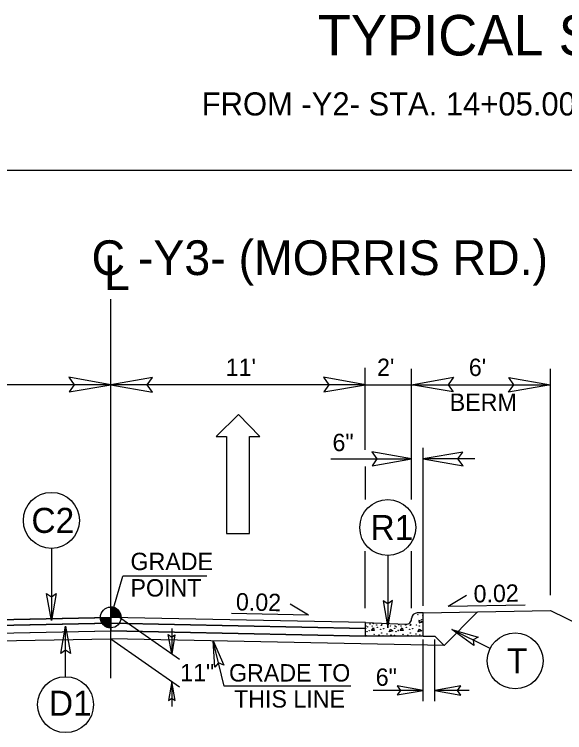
# Model space of a CAD drawing. Extents: x 1487909 to 1489267, y 497866 to 499814.
# Drawn here: x 1488976.3 to 1489000.07, y 498034.86 to 498065.88 of the extents above; entities that cross this region are included whole.
import ezdxf

# ---------------------------------------------------------------- set-up
doc = ezdxf.new("R2010")
doc.units = 0
for name, color, linetype in [('Old_Level_10', 7, 'Continuous'), ('Prop Dimension', 7, 'Continuous'), ('Prop Dimension Text', 7, 'Continuous'), ('Prop Lane Arrow CELL', 7, 'Continuous'), ('Prop Shade Light', 7, 'Continuous'), ('Prop Terminator CELL', 7, 'Continuous'), ('Scratch_Level_1', 7, 'Continuous'), ('Typical Curb CELL', 7, 'Continuous'), ('Typical Detail Wedge2 CELL', 7, 'Continuous'), ('Typical Grade Point Symbol CELL', 7, 'Continuous'), ('Typical Hinge Slope Arterial CELL', 7, 'Continuous'), ('Typical Hinge Slope Interstate CELL', 7, 'Continuous'), ('Typical ID Circle CELL', 7, 'Continuous'), ('Typical Pavement Slope CELL', 7, 'Continuous'), ('Typical Pavement Slope Information CELL', 7, 'Continuous'), ('Typical Terminator CELL', 7, 'Continuous'), ('Typical Text Grade Point CELL', 7, 'Continuous'), ('Typical Text ID Circle CELL', 7, 'Continuous')]:
    doc.layers.add(name, color=color, linetype=linetype)

msp = doc.modelspace()

# ---------------------------------------------------------------- linework, layer by layer
at = {"layer": 'Old_Level_10'}
for p, q in [((1488980.464, 498039.58), (1488969.464, 498039.36)), ((1488980.464, 498039.247), (1488980.464, 498039.58)), ((1488980.464, 498039.58), (1488980.464, 498039.247)), ((1488991.464, 498039.36), (1488980.464, 498039.58)), ((1488980.464, 498039.58), (1488980.464, 498039.58)), ((1488974.963, 498039.137), (1488980.464, 498039.247)), ((1488980.464, 498039.247), (1488985.964, 498039.137)), ((1488985.964, 498039.137), (1488991.464, 498039.027)), ((1488991.464, 498039.027), (1488991.464, 498039.36))]:
    msp.add_line(p, q, dxfattribs=at)
at = {"layer": 'Prop Dimension'}
for p, q in [((1488980.464, 498037.215), (1488980.464, 498053.576)), ((1488991.463, 498047.07), (1488991.463, 498050.612)), ((1488993.464, 498044.924), (1488993.464, 498050.568)), ((1488999.464, 498040.793), (1488999.464, 498050.568)), ((1488980.464, 498049.887), (1488969.464, 498049.887)), ((1488991.464, 498049.887), (1488980.464, 498049.887)), ((1488991.464, 498049.887), (1488993.464, 498049.887)), ((1488993.464, 498049.887), (1488999.464, 498049.887)), ((1488993.963, 498040.339), (1488993.963, 498047.152)), ((1488989.968, 498046.681), (1488993.463, 498046.681)), ((1488996.2, 498046.681), (1488993.963, 498046.681)), ((1488991.464, 498044.924), (1488991.464, 498046.354)), ((1488991.463, 498040.231), (1488991.463, 498042.701)), ((1488993.463, 498040.231), (1488993.463, 498042.701)), ((1488985.367, 498036.869), (1488984.883, 498038.826)), ((1488993.963, 498036.221), (1488993.963, 498038.875)), ((1488994.463, 498036.221), (1488994.463, 498038.875)), ((1488990.84, 498036.869), (1488985.367, 498036.869)), ((1488993.963, 498036.68), (1488991.802, 498036.68)), ((1488995.95, 498036.68), (1488994.463, 498036.68))]:
    msp.add_line(p, q, dxfattribs=at)
at = {"layer": 'Prop Dimension Text'}
for p in [(1488980.464, 498039.83), (1488984.608, 498041.62)]:
    msp.add_line(p, (1488980.989, 498041.62), dxfattribs=at)
at = {"layer": 'Prop Lane Arrow CELL'}
for p, q in [((1488985.979, 498048.6), (1488985.019, 498047.655)), ((1488986.909, 498047.655), (1488985.979, 498048.6)), ((1488985.019, 498047.655), (1488985.469, 498047.655)), ((1488985.469, 498047.655), (1488985.469, 498043.455)), ((1488986.459, 498043.455), (1488986.459, 498047.655)), ((1488986.459, 498047.655), (1488986.909, 498047.655)), ((1488985.469, 498043.455), (1488986.459, 498043.455))]:
    msp.add_line(p, q, dxfattribs=at)
at = {"layer": 'Prop Shade Light'}
for p, q in [((1488980.464, 498039.83), (1488969.464, 498039.61)), ((1488980.464, 498039.58), (1488980.464, 498039.83)), ((1488991.464, 498039.61), (1488980.464, 498039.83)), ((1488980.464, 498039.83), (1488980.464, 498039.58)), ((1488969.464, 498039.36), (1488980.464, 498039.58)), ((1488980.464, 498039.58), (1488991.464, 498039.36)), ((1488991.464, 498039.36), (1488991.464, 498039.61))]:
    msp.add_line(p, q, dxfattribs=at)
at = {"layer": 'Prop Terminator CELL'}
for points in [[(1488978.664, 498049.577), (1488980.464, 498049.887), (1488978.654, 498050.207), (1488978.884, 498049.887)], [(1488982.264, 498050.197), (1488980.464, 498049.887), (1488982.274, 498049.567), (1488982.044, 498049.887)], [(1488989.664, 498049.577), (1488991.464, 498049.887), (1488989.654, 498050.207), (1488989.884, 498049.887)], [(1488995.264, 498049.577), (1488993.464, 498049.887), (1488995.274, 498050.207), (1488995.044, 498049.887)], [(1488997.664, 498050.197), (1488999.464, 498049.887), (1488997.654, 498049.567), (1488997.884, 498049.887)], [(1488991.753, 498046.387), (1488993.463, 498046.681), (1488991.744, 498046.985), (1488991.962, 498046.681)], [(1488995.673, 498046.976), (1488993.963, 498046.681), (1488995.683, 498046.377), (1488995.464, 498046.681)], [(1488984.965, 498037.687), (1488984.883, 498038.826), (1488985.349, 498037.776), (1488985.12, 498037.867)], [(1488992.838, 498036.487), (1488993.963, 498036.68), (1488992.832, 498036.88), (1488992.976, 498036.68)], [(1488995.588, 498036.874), (1488994.463, 498036.68), (1488995.594, 498036.48), (1488995.451, 498036.68)]]:
    msp.add_lwpolyline(points, close=True, dxfattribs=at)
at = {"layer": 'Scratch_Level_1'}
msp.add_line((1488899.964, 498059.154), (1489049.964, 498059.154), dxfattribs=at)
at = {"layer": 'Typical Curb CELL'}
for p, q in [((1488993.963, 498040.027), (1488993.703, 498040.027)), ((1488993.963, 498039.027), (1488993.963, 498040.027)), ((1488993.463, 498039.777), (1488993.463, 498039.787)), ((1488991.464, 498039.027), (1488991.464, 498039.61)), ((1488991.464, 498039.61), (1488993.214, 498039.537)), ((1488993.773, 498039.694), (1488993.789, 498039.603)), ((1488993.927, 498039.649), (1488993.773, 498039.694)), ((1488993.789, 498039.603), (1488993.927, 498039.649)), ((1488991.724, 498039.267), (1488991.81, 498039.386)), ((1488991.845, 498039.273), (1488991.724, 498039.267)), ((1488991.81, 498039.386), (1488991.845, 498039.273)), ((1488992.489, 498039.216), (1488992.552, 498039.33)), ((1488992.655, 498039.255), (1488992.489, 498039.216)), ((1488992.552, 498039.33), (1488992.655, 498039.255)), ((1488992.974, 498039.267), (1488993.059, 498039.386)), ((1488993.094, 498039.273), (1488992.974, 498039.267)), ((1488993.059, 498039.386), (1488993.094, 498039.273)), ((1488993.738, 498039.216), (1488993.801, 498039.33)), ((1488993.904, 498039.255), (1488993.738, 498039.216)), ((1488993.801, 498039.33), (1488993.904, 498039.255)), ((1488993.963, 498039.027), (1488991.464, 498039.027))]:
    msp.add_line(p, q, dxfattribs=at)
for centre in [(1488993.733, 498039.951), (1488993.898, 498039.734), (1488993.95, 498039.917), (1488991.497, 498039.461), (1488991.553, 498039.427), (1488991.662, 498039.552), (1488991.759, 498039.467), (1488991.804, 498039.569), (1488991.953, 498039.506), (1488991.981, 498039.404), (1488992.158, 498039.49), (1488992.175, 498039.54), (1488992.432, 498039.512), (1488992.552, 498039.461), (1488992.746, 498039.461), (1488992.802, 498039.427), (1488992.911, 498039.521), (1488993.008, 498039.467), (1488993.202, 498039.506), (1488993.23, 498039.404), (1488993.407, 498039.49), (1488993.425, 498039.54), (1488993.681, 498039.512), (1488993.801, 498039.461), (1488991.48, 498039.364), (1488991.537, 498039.221), (1488991.633, 498039.267), (1488991.844, 498039.101), (1488992.13, 498039.318), (1488992.164, 498039.164), (1488992.256, 498039.347), (1488992.398, 498039.113), (1488992.729, 498039.364), (1488992.786, 498039.221), (1488992.882, 498039.267), (1488993.093, 498039.101), (1488993.379, 498039.318), (1488993.413, 498039.164), (1488993.505, 498039.347), (1488993.647, 498039.113), (1488991.474, 498039.056), (1488991.685, 498039.033), (1488992.05, 498039.079), (1488992.221, 498039.05), (1488992.569, 498039.073), (1488992.723, 498039.056), (1488992.934, 498039.033), (1488993.299, 498039.079), (1488993.47, 498039.05), (1488993.818, 498039.073)]:
    msp.add_circle(centre, 0.00802, dxfattribs=at)
for centre, start, end in [((1488993.703, 498039.787), 90, 180), ((1488993.224, 498039.777), 267.6155, 0)]:
    msp.add_arc(centre, 0.24, start, end, dxfattribs=at)
at = {"layer": 'Typical Detail Wedge2 CELL'}
for p, q in [((1488980.464, 498040.11), (1488983.428, 498038.034)), ((1488983.096, 498039.351), (1488983.096, 498038.266)), ((1488980.464, 498038.914), (1488983.428, 498036.839)), ((1488983.107, 498037.063), (1488983.107, 498035.979))]:
    msp.add_line(p, q, dxfattribs=at)
at = {"layer": 'Typical Grade Point Symbol CELL'}
for p, q in [((1488980.464, 498039.83), (1488980.464, 498040.278)), ((1488980.016, 498039.83), (1488980.464, 498039.83)), ((1488980.463, 498039.383), (1488980.464, 498039.83)), ((1488980.464, 498039.83), (1488980.463, 498039.383)), ((1488980.911, 498039.83), (1488980.464, 498039.83))]:
    msp.add_line(p, q, dxfattribs=at)
for points in [[(1488980.468, 498040.278), (1488980.468, 498040.278), (1488980.468, 498039.83)], [(1488980.477, 498040.278), (1488980.477, 498039.83)], [(1488980.486, 498040.277), (1488980.486, 498039.83)], [(1488980.494, 498040.277), (1488980.494, 498039.83)], [(1488980.503, 498040.276), (1488980.503, 498039.83)], [(1488980.512, 498040.275), (1488980.512, 498039.83)], [(1488980.521, 498040.274), (1488980.521, 498039.83)], [(1488980.53, 498040.273), (1488980.53, 498039.83)], [(1488980.539, 498040.272), (1488980.539, 498039.83)], [(1488980.548, 498040.27), (1488980.548, 498039.83)], [(1488980.557, 498040.268), (1488980.557, 498039.83)], [(1488980.566, 498040.266), (1488980.566, 498039.83)], [(1488980.575, 498040.264), (1488980.575, 498039.83)], [(1488980.584, 498040.261), (1488980.584, 498039.83)], [(1488980.593, 498040.259), (1488980.593, 498039.83)], [(1488980.602, 498040.256), (1488980.602, 498039.83)], [(1488980.611, 498040.253), (1488980.611, 498039.83)], [(1488980.62, 498040.25), (1488980.62, 498039.83)], [(1488980.629, 498040.246), (1488980.629, 498039.83)], [(1488980.638, 498040.242), (1488980.638, 498039.83)], [(1488980.647, 498040.238), (1488980.647, 498039.83)], [(1488980.656, 498040.234), (1488980.656, 498039.83)], [(1488980.665, 498040.23), (1488980.665, 498039.83)], [(1488980.673, 498040.225), (1488980.673, 498039.83)], [(1488980.682, 498040.22), (1488980.682, 498039.83)], [(1488980.691, 498040.215), (1488980.691, 498039.83)], [(1488980.7, 498040.21), (1488980.7, 498039.83)], [(1488980.709, 498040.204), (1488980.709, 498039.83)], [(1488980.718, 498040.198), (1488980.718, 498039.83)], [(1488980.727, 498040.191), (1488980.727, 498039.83)], [(1488980.736, 498040.185), (1488980.736, 498039.83)], [(1488980.745, 498040.178), (1488980.745, 498039.83)], [(1488980.754, 498040.17), (1488980.754, 498039.83)], [(1488980.763, 498040.163), (1488980.763, 498039.83)], [(1488980.772, 498040.155), (1488980.772, 498039.83)], [(1488980.781, 498040.146), (1488980.781, 498039.83)], [(1488980.79, 498040.137), (1488980.79, 498039.83)], [(1488980.799, 498040.127), (1488980.799, 498039.83)], [(1488980.808, 498040.116), (1488980.808, 498039.83)], [(1488980.817, 498040.105), (1488980.817, 498039.83)], [(1488980.826, 498040.093), (1488980.826, 498039.83)], [(1488980.835, 498040.08), (1488980.835, 498039.83)], [(1488980.844, 498040.066), (1488980.844, 498039.83)], [(1488980.852, 498040.051), (1488980.852, 498039.83)], [(1488980.861, 498040.035), (1488980.861, 498039.83)], [(1488980.018, 498039.83), (1488980.018, 498039.782)], [(1488980.027, 498039.83), (1488980.027, 498039.729)], [(1488980.036, 498039.83), (1488980.036, 498039.697)], [(1488980.045, 498039.83), (1488980.045, 498039.67)], [(1488980.054, 498039.83), (1488980.054, 498039.649)], [(1488980.063, 498039.83), (1488980.063, 498039.63)], [(1488980.072, 498039.83), (1488980.072, 498039.613)], [(1488980.081, 498039.83), (1488980.081, 498039.598)], [(1488980.09, 498039.83), (1488980.09, 498039.584)], [(1488980.099, 498039.83), (1488980.099, 498039.571)], [(1488980.108, 498039.83), (1488980.108, 498039.559)], [(1488980.116, 498039.83), (1488980.116, 498039.548)], [(1488980.125, 498039.83), (1488980.125, 498039.537)], [(1488980.134, 498039.83), (1488980.134, 498039.527)], [(1488980.143, 498039.83), (1488980.143, 498039.517)], [(1488980.152, 498039.83), (1488980.152, 498039.508)], [(1488980.161, 498039.83), (1488980.161, 498039.5)], [(1488980.17, 498039.83), (1488980.17, 498039.492)], [(1488980.179, 498039.83), (1488980.179, 498039.484)], [(1488980.188, 498039.83), (1488980.188, 498039.477)], [(1488980.197, 498039.83), (1488980.197, 498039.47)], [(1488980.206, 498039.83), (1488980.206, 498039.464)], [(1488980.215, 498039.83), (1488980.215, 498039.458)], [(1488980.224, 498039.83), (1488980.224, 498039.452)], [(1488980.233, 498039.83), (1488980.233, 498039.446)], [(1488980.242, 498039.83), (1488980.242, 498039.441)], [(1488980.251, 498039.83), (1488980.251, 498039.436)], [(1488980.26, 498039.83), (1488980.26, 498039.431)], [(1488980.269, 498039.83), (1488980.269, 498039.427)], [(1488980.278, 498039.83), (1488980.278, 498039.423)], [(1488980.287, 498039.83), (1488980.287, 498039.419)], [(1488980.295, 498039.83), (1488980.295, 498039.416)], [(1488980.304, 498039.83), (1488980.304, 498039.412)], [(1488980.313, 498039.83), (1488980.313, 498039.409)], [(1488980.322, 498039.83), (1488980.322, 498039.406)], [(1488980.331, 498039.83), (1488980.331, 498039.403)], [(1488980.34, 498039.83), (1488980.34, 498039.401)], [(1488980.349, 498039.83), (1488980.349, 498039.398)], [(1488980.358, 498039.83), (1488980.358, 498039.396)], [(1488980.367, 498039.83), (1488980.367, 498039.394)], [(1488980.376, 498039.83), (1488980.376, 498039.392)], [(1488980.385, 498039.83), (1488980.385, 498039.39)], [(1488980.394, 498039.83), (1488980.394, 498039.389)], [(1488980.403, 498039.83), (1488980.403, 498039.387)], [(1488980.412, 498039.83), (1488980.412, 498039.386)], [(1488980.421, 498039.83), (1488980.421, 498039.385)], [(1488980.43, 498039.83), (1488980.43, 498039.384)], [(1488980.439, 498039.83), (1488980.439, 498039.384)], [(1488980.448, 498039.83), (1488980.448, 498039.383)], [(1488980.457, 498039.83), (1488980.457, 498039.383), (1488980.457, 498039.383)], [(1488980.87, 498040.016), (1488980.87, 498039.83)], [(1488980.879, 498039.995), (1488980.879, 498039.83)], [(1488980.888, 498039.97), (1488980.888, 498039.83)], [(1488980.897, 498039.94), (1488980.897, 498039.83)], [(1488980.906, 498039.894), (1488980.906, 498039.83)]]:
    msp.add_lwpolyline(points, dxfattribs=at)
msp.add_circle((1488980.463, 498039.83), 0.448, dxfattribs=at)
for start, end in [(359.9905, 89.9905), (179.9905, 269.9905)]:
    msp.add_arc((1488980.463, 498039.83), 0.448, start, end, dxfattribs=at)
at = {"layer": 'Typical Hinge Slope Arterial CELL'}
msp.add_line((1488999.464, 498040.137), (1489003.978, 498037.88), dxfattribs=at)
at = {"layer": 'Typical ID Circle CELL'}
for p, q in [((1488977.899, 498042.817), (1488977.899, 498039.694)), ((1488992.431, 498042.507), (1488992.431, 498039.384)), ((1488978.513, 498037.273), (1488978.513, 498039.45)), ((1488996.853, 498038.493), (1488995.196, 498039.317))]:
    msp.add_line(p, q, dxfattribs=at)
for centre in [(1488977.899, 498044.025), (1488992.431, 498043.716), (1488997.935, 498037.955), (1488978.513, 498036.065)]:
    msp.add_circle(centre, 1.208, dxfattribs=at)
at = {"layer": 'Typical Pavement Slope CELL'}
for p, q in [((1488993.963, 498040.027), (1488999.464, 498040.137)), ((1488996.313, 498040.074), (1488994.865, 498038.626)), ((1488969.464, 498039.61), (1488980.464, 498039.83)), ((1488991.464, 498039.61), (1488980.464, 498039.83)), ((1488969.464, 498039.36), (1488980.464, 498039.58)), ((1488991.464, 498039.36), (1488980.464, 498039.58)), ((1488969.464, 498039.027), (1488980.464, 498039.247)), ((1488991.464, 498039.027), (1488980.464, 498039.247)), ((1488966.063, 498038.626), (1488980.464, 498038.914)), ((1488994.865, 498038.626), (1488980.464, 498038.914)), ((1488993.963, 498039.027), (1488994.463, 498039.027)), ((1488994.463, 498039.027), (1488994.865, 498038.626))]:
    msp.add_line(p, q, dxfattribs=at)
at = {"layer": 'Typical Pavement Slope Information CELL'}
for p, q in [((1488995.049, 498040.315), (1488995.832, 498040.788)), ((1488989.001, 498039.937), (1488988.218, 498040.41)), ((1488995.049, 498040.315), (1488998.366, 498040.381)), ((1488989.001, 498039.937), (1488985.685, 498040.003))]:
    msp.add_line(p, q, dxfattribs=at)
at = {"layer": 'Typical Terminator CELL'}
for points in [[(1488978.101, 498040.865), (1488977.899, 498039.694), (1488977.69, 498040.872), (1488977.899, 498040.722)], [(1488992.229, 498040.556), (1488992.431, 498039.384), (1488992.64, 498040.562), (1488992.431, 498040.413)], [(1488978.311, 498038.279), (1488978.513, 498039.45), (1488978.721, 498038.272), (1488978.513, 498038.422)], [(1488996.155, 498038.615), (1488995.196, 498039.317), (1488996.344, 498038.979), (1488996.117, 498038.859)], [(1488983.237, 498039.087), (1488983.096, 498038.266), (1488982.95, 498039.091), (1488983.096, 498038.986)], [(1488983.248, 498036.243), (1488983.107, 498037.063), (1488982.961, 498036.238), (1488983.107, 498036.343)]]:
    msp.add_lwpolyline(points, close=True, dxfattribs=at)

# ---------------------------------------------------------------- texts
at = {"layer": 'Prop Dimension Text'}
for s, p in [("11'", (1488985.431, 498050.261)), ("2'", (1488991.969, 498050.261)), ("6'", (1488995.935, 498050.261)), ('BERM', (1488995.11, 498048.753)), ('6"', (1488990.044, 498047.017)), ('11"', (1488983.463, 498037.078)), ('GRADE TO', (1488985.574, 498037.064)), ('6"', (1488991.912, 498036.879)), ('THIS LINE', (1488985.792, 498035.939))]:
    msp.add_text(s, height=0.75, dxfattribs=at).set_placement(p)
at = {"layer": 'Typical Hinge Slope Arterial CELL'}
msp.add_text('FROM -Y2- STA. 14+05.00 TO STA. 15+30.00', height=1, dxfattribs=at).set_placement((1488984.394, 498061.515))
at = {"layer": 'Typical Hinge Slope Interstate CELL'}
for s, p in [('C -Y3- (MORRIS RD.)', (1488979.633, 498054.622)), ('L', (1488980.173, 498053.973))]:
    msp.add_text(s, height=1.5, dxfattribs=at).set_placement(p)
at = {"layer": 'Typical Pavement Slope CELL'}
msp.add_text('TYPICAL SECTION 8', height=1.75, dxfattribs=at).set_placement((1488989.41, 498064.107))
at = {"layer": 'Typical Pavement Slope Information CELL'}
for rotation, p in [(1.1457, (1488996.147, 498040.476)), (358.8543, (1488985.865, 498040.138))]:
    msp.add_text('0.02', height=0.75, rotation=rotation, dxfattribs=at).set_placement(p)
at = {"layer": 'Typical Text Grade Point CELL'}
for s, p in [('GRADE', (1488981.317, 498041.877)), ('POINT', (1488981.317, 498040.736))]:
    msp.add_text(s, height=0.75, dxfattribs=at).set_placement(p)
at = {"layer": 'Typical Text ID Circle CELL'}
for s, height, p in [('C2', 1.0817, (1488977.037, 498043.484)), ('R1', 1.0817, (1488991.687, 498043.175)), ('T', 1.082, (1488997.58, 498037.414)), ('D1', 1.0817, (1488977.792, 498035.586))]:
    msp.add_text(s, height=height, dxfattribs=at).set_placement(p)

doc.saveas('drawing.dxf')
